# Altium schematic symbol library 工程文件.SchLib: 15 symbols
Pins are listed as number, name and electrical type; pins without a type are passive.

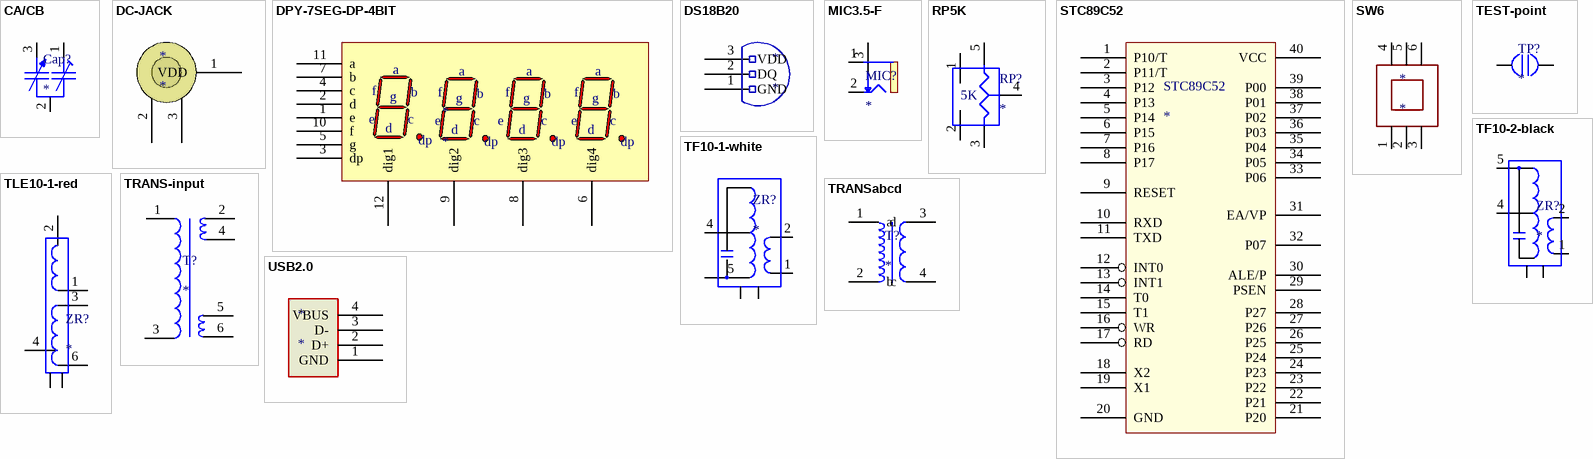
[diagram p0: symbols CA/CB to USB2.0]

## CA/CB
designator Cap?
footprint CA/CB
pins: 1 2, 2 1, 3 2

## DC-JACK
designator *
pins: 1 VDD, 2 GND, 3 GND

## DPY-7SEG-DP-4BIT
designator *
pins: 1 e, 2 d, 3 dp, 4 c, 5 g, 6 dig4, 7 b, 8 dig3, 9 dig2, 10 f, 11 a, 12 dig1

## DS18B20
designator *
pins: 1 GND, 2 DQ, 3 VDD

## MIC3.5-F
designator MIC?
footprint MIC3.5-F
pins: 1 42, 2 44, 3 43

## RP5K
designator RP?
footprint RP5K
pins: 1 K1, 2 K2, 3 B, 4 TAP, 5 A

## STC89C52
designator STC89C52
pins: 1 P10/T, 2 P11/T, 3 P12, 4 P13, 5 P14, 6 P15, 7 P16, 8 P17, 9 RESET, 10 RXD, 11 TXD, 12 INT0, 13 INT1, 14 T0, 15 T1, 16 WR, 17 RD, 18 X2, 19 X1, 20 GND, 21 P20, 22 P21, 23 P22, 24 P23, 25 P24, 26 P25, 27 P26, 28 P27, 29 PSEN, 30 ALE/P, 31 EA/VP, 32 P07, 33 P06, 34 P05, 35 P04, 36 P03, 37 P02, 38 P01, 39 P00, 40 VCC

## SW6
designator *
pins: 1, 2, 3, 4, 5, 6

## TEST-point
designator TP?
footprint TEST-point
pins: 1, 2

## TF10-1-white
designator ZR?
footprint TF10-1-white
pins: 1, 2, 3, 4, 5, 6, 7

## TF10-2-black
designator ZR?
footprint TF10-2-black
pins: 1, 2, 3, 4, 5, 6, 7

## TLE10-1-red
designator ZR?
footprint TLE10-1-red
pins: 1, 2, 3, 4, 5, 6 3, 7

## TRANS-input
designator T?
footprint TRANS-input
pins: 1, 2, 3, 4, 5, 6

## TRANSabcd
designator T?
pins: 1 a, 2 b, 3 d, 4 c

## USB2.0
designator *
pins: 1 GND, 2 D+, 3 D-, 4 VBUS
